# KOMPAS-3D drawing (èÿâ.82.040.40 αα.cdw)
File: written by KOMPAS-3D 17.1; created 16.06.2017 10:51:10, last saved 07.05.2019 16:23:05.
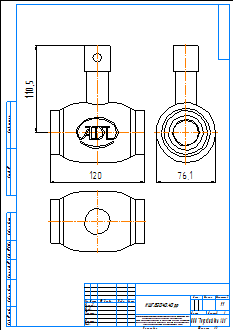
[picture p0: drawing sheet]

Sheet 1: A3, portrait

Title block, sheet 1: name: КШГ.82.040.40 рр; material: Внимание! Данный продукт является объектом авторского права ООО «Торговый Дом АДЛ». / Запрещается изменение, копирование, распространение / (в том числе путем копирования на другие сайты и ресурсы в Интернете) / или любое иное использование информации и объектов без предварительного / согласия правообладателя (ООО «Торговый Дом АДЛ»).; scale: 1:1; sheets: 1; organisation: ООО "Торговый дом АДЛ"; sheet format: A3; stored path: C:\Users\tra\Desktop\2д чертежи\Шаровые краны БИВАЛ\КШ_Бивал_серия_82_85\KOMPAS 2D\КШГ.82.040.40 рр.cdw

Views: Спереди 1, Проекционный вид 2, Проекционный вид 3
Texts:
  Klimkovich
  ADL
Dimensions and other numbers on the sheet: 120; 110,5; 76,1; 1:1; 1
